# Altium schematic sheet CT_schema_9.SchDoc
size 287 x 160 mm
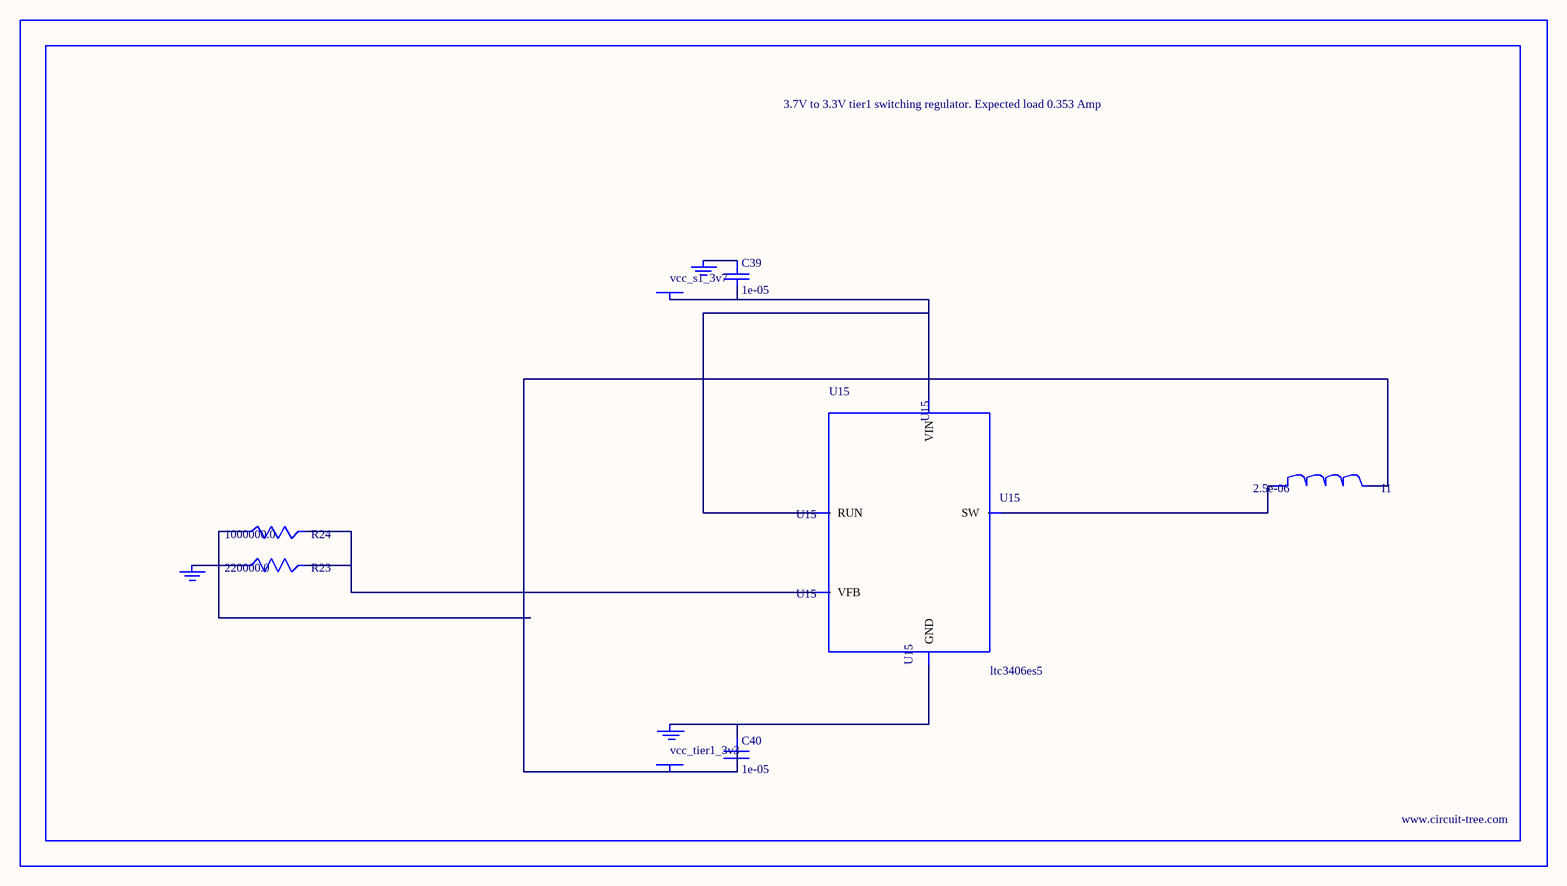
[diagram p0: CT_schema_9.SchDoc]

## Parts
BORDER8  (no value)
C39  1e-05  [C0805]
C40  1e-05  [C0805]
GND_INSTANCE_8_0  (no value)
GND_INSTANCE_8_1  (no value)
GND_INSTANCE_8_2  (no value)
I1  2.5e-06  [DR1040]
POWER_INSTANCE_8_0  vcc_tier1_3v3
POWER_INSTANCE_8_1  vcc_s1_3v7
R23  220000.0  [R0603]
R24  1000000.0  [R0603]
U15  ltc3406es5  [TSOT-23-5]

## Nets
NetC39_1: C39.1 GND_INSTANCE_8_1.0(GND)
NetC39_2: C39.2 POWER_INSTANCE_8_1.0(PWR) U15.1(RUN) U15.4(VIN)
NetC40_1: C40.1 GND_INSTANCE_8_0.0(GND) U15.2(GND)
NetC40_2: C40.2 I1.2 POWER_INSTANCE_8_0.0(PWR) R24.1
NetGND_INSTANCE_8_2_0: GND_INSTANCE_8_2.0(GND) R23.1
NetI1_1: I1.1 U15.3(SW)
NetR23_2: R23.2 R24.2 U15.5(VFB)

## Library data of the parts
BORDER8 = BORDER_PAGE8
C39 C40 = C0805C106K8RACTU
GND_INSTANCE_8_0-GND_INSTANCE_8_2 = GND
I1 = DR1040-2R5-R
POWER_INSTANCE_8_0 POWER_INSTANCE_8_1 = PWR
R23 = RC0603JR-07220KL
R24 = RC0603JR-071ML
